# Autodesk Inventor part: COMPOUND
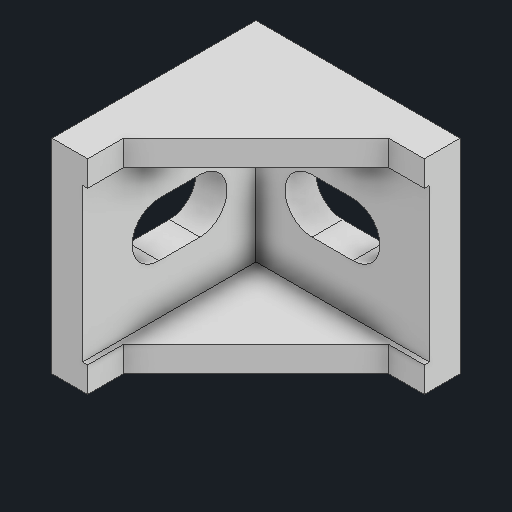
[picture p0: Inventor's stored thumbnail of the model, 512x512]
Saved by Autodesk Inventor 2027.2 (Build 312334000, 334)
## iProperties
Created: 2026-11
Part Number: COMPOUND
Material: Genérico
Document SubType Name: Modeling
Designer: Usuario
Density: 1 g/cm^3
Appearance: Valor por defecto
Author: Usuario
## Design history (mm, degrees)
feature "Base1"
node "Sólido1"
